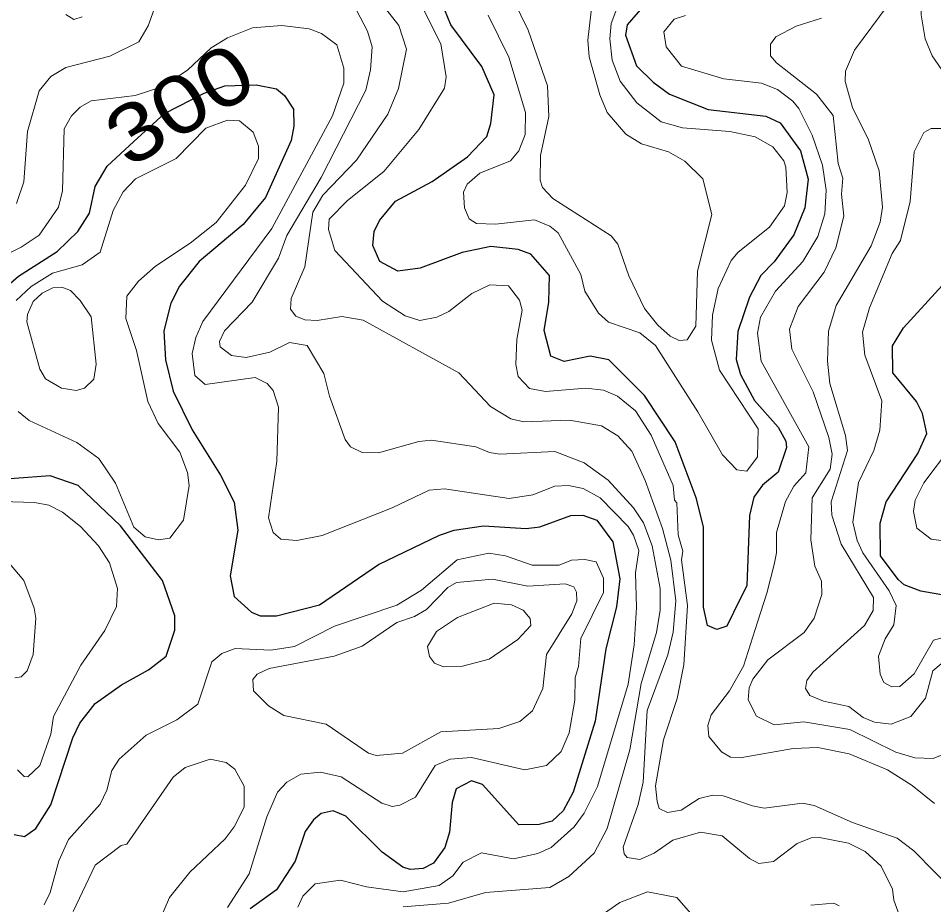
# Model space of a CAD drawing. Extents: x 673.6 to 698.9, y 7012 to 7040.1.
# Drawn here: x 684.723 to 685.993, y 7015.399 to 7016.628 of the extents above; entities that cross this region are included whole.
import ezdxf
from ezdxf.enums import TextEntityAlignment as Align

# ---------------------------------------------------------------- set-up
doc = ezdxf.new("R2010")
doc.units = 0
doc.header["$LTSCALE"] = 0.032
doc.layers.add('1', color=7, linetype='Continuous', lineweight=25)
doc.layers.add('2', color=7, linetype='Continuous', lineweight=13)
doc.layers.add('61', color=7, linetype='Continuous')

msp = doc.modelspace()

# ---------------------------------------------------------------- linework, layer by layer
at = {"layer": '1'}
for points in [[(685.7717, 7016.2906), (685.7529, 7016.2715), (685.7372, 7016.2417), (685.7212, 7016.1938), (685.7189, 7016.1552), (685.7249, 7016.1342), (685.7441, 7016.0984), (685.7771, 7016.061), (685.7876, 7016.0417), (685.7886, 7016.0331), (685.777, 7015.999), (685.7552, 7015.9808), (685.7432, 7015.964), (685.7376, 7015.9386), (685.7335, 7015.8419), (685.7153, 7015.8044), (685.7058, 7015.7855), (685.6923, 7015.7805), (685.679, 7015.7862), (685.6736, 7015.8118), (685.6735, 7015.923), (685.6635, 7015.9634), (685.6343, 7016.041), (685.5917, 7016.1051), (685.5425, 7016.1548), (685.5163, 7016.1595), (685.4802, 7016.1524), (685.4621, 7016.1595), (685.4526, 7016.1954), (685.4592, 7016.2345), (685.46, 7016.2715), (685.434, 7016.3011), (685.4168, 7016.3075), (685.3786, 7016.3117), (685.3391, 7016.3035), (685.2809, 7016.2816), (685.2495, 7016.2773), (685.2248, 7016.2907), (685.2151, 7016.3129), (685.217, 7016.3326), (685.2244, 7016.3479), (685.2466, 7016.3745), (685.2971, 7016.4018), (685.3461, 7016.436), (685.3732, 7016.4641), (685.3787, 7016.4822), (685.3832, 7016.522), (685.366, 7016.5611), (685.3233, 7016.6191), (685.3147, 7016.6393)], [(685.5892, 7016.6436), (685.5677, 7016.6191), (685.5652, 7016.6047), (685.5809, 7016.5624), (685.6037, 7016.5395), (685.6263, 7016.5228), (685.6802, 7016.5018), (685.7599, 7016.4924), (685.7799, 7016.4831)], [(684.705, 7016.2544), (684.7238, 7016.2708), (684.7771, 7016.3046), (684.8058, 7016.3323), (684.8223, 7016.3581), (684.8298, 7016.3951), (684.8465, 7016.4229), (684.8837, 7016.4572), (684.9263, 7016.496), (684.9813, 7016.5244), (685.0097, 7016.5345), (685.0532, 7016.536), (685.0816, 7016.5304), (685.0926, 7016.5212), (685.1048, 7016.5023), (685.1057, 7016.4786), (685.1016, 7016.4588), (685.0661, 7016.3796), (685.0354, 7016.3424), (684.9741, 7016.2908), (684.9469, 7016.2566), (684.9347, 7016.2333), (684.925, 7016.1946), (684.9274, 7016.1547), (684.9382, 7016.1112), (684.9644, 7016.0576), (685.0037, 7015.9945), (685.0229, 7015.9572), (685.0277, 7015.9182), (685.0172, 7015.8552), (685.0227, 7015.8264), (685.047, 7015.8046), (685.0586, 7015.7998), (685.0815, 7015.7998), (685.1411, 7015.815), (685.2228, 7015.8706), (685.3076, 7015.9114), (685.328, 7015.9182), (685.3683, 7015.9246), (685.4275, 7015.9206), (685.4467, 7015.9229), (685.4895, 7015.9387), (685.5064, 7015.9394), (685.5257, 7015.9323), (685.5479, 7015.9021), (685.5577, 7015.8508)], [(685.7799, 7016.4831), (685.8082, 7016.4444), (685.8189, 7016.405), (685.8141, 7016.3651), (685.7989, 7016.3281), (685.7717, 7016.2906)], [(685.975, 7015.8339), (685.9518, 7015.8428), (685.9434, 7015.8498), (685.919, 7015.8828), (685.9185, 7015.928), (685.9269, 7015.9579), (685.9708, 7016.0246), (685.9833, 7016.0525), (685.9771, 7016.08), (685.9688, 7016.0969), (685.936, 7016.1364), (685.9355, 7016.1741), (685.9511, 7016.199), (686.0047, 7016.2576)], [(684.7177, 7015.4966), (684.7319, 7015.4935), (684.7479, 7015.5046), (684.7684, 7015.5376), (684.7991, 7015.6304), (684.8089, 7015.651), (684.8298, 7015.678), (684.8667, 7015.704), (684.9041, 7015.7247), (684.9286, 7015.7438), (684.9405, 7015.78), (684.9406, 7015.7996), (684.9235, 7015.8487), (684.8649, 7015.9242), (684.8065, 7015.9805), (684.7676, 7015.9936), (684.668, 7015.9863)], [(685.5577, 7015.8508), (685.553, 7015.8122), (685.5383, 7015.7537), (685.5232, 7015.6535), (685.4928, 7015.555), (685.4791, 7015.5292)], [(686.1946, 7015.8512), (686.1607, 7015.8411), (686.1026, 7015.8392), (686.0479, 7015.8302), (686.0094, 7015.8278), (685.975, 7015.8339)], [(685.4791, 7015.5292), (685.4637, 7015.5151), (685.4456, 7015.5105), (685.4173, 7015.5099), (685.367, 7015.5659), (685.352, 7015.5707), (685.3307, 7015.5597), (685.3251, 7015.5408), (685.3214, 7015.4997), (685.3149, 7015.4785), (685.299, 7015.4567), (685.2849, 7015.4491), (685.2669, 7015.4481), (685.2567, 7015.4512), (685.2282, 7015.4721), (685.1778, 7015.5219), (685.16, 7015.5293), (685.1435, 7015.5257), (685.1326, 7015.5167), (685.1214, 7015.5006), (685.1074, 7015.4596), (685.0815, 7015.4196), (685.0447, 7015.3935)]]:
    msp.add_lwpolyline(points, dxfattribs=at)
at = {"layer": '2'}
for points in [[(685.2143, 7016.5886), (685.2075, 7016.6103), (685.1818, 7016.66), (685.1425, 7016.7188), (685.1023, 7016.7673), (685.0626, 7016.8407)], [(686.035, 7016.5117), (685.9907, 7016.5761), (685.9811, 7016.5998), (685.9753, 7016.6327), (685.9769, 7016.686), (685.9833, 7016.7198), (686.0017, 7016.7616)], [(684.9289, 7016.6886), (684.9035, 7016.6179), (684.8907, 7016.5957), (684.8501, 7016.5758), (684.7893, 7016.5601), (684.7686, 7016.5473), (684.7525, 7016.5277), (684.7362, 7016.4711), (684.731, 7016.4013), (684.7211, 7016.3714)], [(685.4031, 7016.2573), (685.3775, 7016.2584), (685.3524, 7016.2467), (685.3205, 7016.2215), (685.3039, 7016.2137), (685.2804, 7016.209), (685.2599, 7016.2157), (685.2285, 7016.2358), (685.1624, 7016.3063), (685.1535, 7016.3352), (685.1547, 7016.3494), (685.18, 7016.3753), (685.2304, 7016.4158), (685.2787, 7016.4738), (685.3145, 7016.5314), (685.3169, 7016.5468), (685.3092, 7016.5926), (685.2752, 7016.6612)], [(685.2274, 7016.648), (685.2512, 7016.6182), (685.2618, 7016.5851), (685.2508, 7016.5307), (685.2358, 7016.4954), (685.1922, 7016.4312), (685.1457, 7016.383), (685.1317, 7016.3595), (685.1206, 7016.2833), (685.102, 7016.2398), (685.1009, 7016.225), (685.1084, 7016.2149), (685.1207, 7016.21), (685.1378, 7016.2091), (685.1719, 7016.2147), (685.2015, 7016.2097), (685.3342, 7016.1366), (685.3783, 7016.0901)], [(685.3749, 7016.6326), (685.4036, 7016.5743), (685.4269, 7016.4973), (685.4262, 7016.4671), (685.4174, 7016.4444), (685.4058, 7016.4303), (685.3636, 7016.4134), (685.346, 7016.3983), (685.3409, 7016.387), (685.3421, 7016.3653), (685.3486, 7016.3502), (685.359, 7016.3438), (685.385, 7016.3425), (685.4391, 7016.3486), (685.4605, 7016.3398), (685.472, 7016.3308), (685.5035, 7016.2731), (685.5092, 7016.25), (685.5278, 7016.2191), (685.542, 7016.207), (685.5854, 7016.1919), (685.6069, 7016.1745), (685.6658, 7016.0823), (685.6998, 7016.0227), (685.72, 7016.0023), (685.7337, 7016.0002), (685.7486, 7016.0203), (685.7493, 7016.0587), (685.6959, 7016.1401), (685.6845, 7016.182), (685.686, 7016.2164), (685.6938, 7016.2533), (685.7121, 7016.2925), (685.7215, 7016.3038), (685.7651, 7016.3383), (685.786, 7016.3682), (685.7894, 7016.3866), (685.7879, 7016.4219), (685.785, 7016.4305), (685.7697, 7016.4498), (685.7454, 7016.4636), (685.7103, 7016.4712), (685.6445, 7016.4761), (685.6148, 7016.4847), (685.581, 7016.5111), (685.5582, 7016.541), (685.5467, 7016.57), (685.5438, 7016.5997), (685.5456, 7016.6207), (685.5576, 7016.6526)], [(685.5179, 7016.6378), (685.5134, 7016.5978), (685.5152, 7016.5748), (685.5296, 7016.522), (685.5401, 7016.4976), (685.5657, 7016.4673), (685.5875, 7016.454), (685.6251, 7016.4432), (685.6478, 7016.4302), (685.6725, 7016.4055), (685.685, 7016.3563), (685.6653, 7016.2777), (685.6629, 7016.2012), (685.6509, 7016.1821), (685.6398, 7016.1812), (685.6273, 7016.1872), (685.6101, 7016.2027), (685.5919, 7016.2256), (685.5702, 7016.2712), (685.5547, 7016.3151), (685.5457, 7016.3263), (685.4647, 7016.3783), (685.4502, 7016.3933), (685.447, 7016.4039), (685.4477, 7016.4378), (685.4591, 7016.4918), (685.4574, 7016.5343), (685.4303, 7016.6116), (685.4101, 7016.6537)], [(685.9298, 7016.6467), (685.883, 7016.584), (685.8707, 7016.5547), (685.8701, 7016.5405), (685.88, 7016.5046), (685.9025, 7016.4594), (685.9174, 7016.4168), (685.9217, 7016.3663), (685.9184, 7016.3455), (685.9061, 7016.3125), (685.8577, 7016.2299)], [(684.7893, 7016.6333), (684.8005, 7016.6265), (684.812, 7016.6301)], [(685.6485, 7016.6322), (685.6331, 7016.627), (685.6186, 7016.6093), (685.622, 7016.5886), (685.6433, 7016.5617), (685.7018, 7016.5444), (685.7541, 7016.5383), (685.7763, 7016.5295), (685.7974, 7016.5133), (685.806, 7016.5029), (685.8243, 7016.4663), (685.8387, 7016.4243), (685.8437, 7016.3898), (685.842, 7016.357), (685.8322, 7016.3257), (685.8114, 7016.291), (685.7736, 7016.2499), (685.7524, 7016.2136), (685.7485, 7016.1917), (685.7534, 7016.1527), (685.8195, 7016.0338), (685.8155, 7015.9979), (685.7988, 7015.9792), (685.7874, 7015.9582), (685.7748, 7015.9152), (685.7747, 7015.8872), (685.7714, 7015.8708), (685.7616, 7015.8309), (685.7486, 7015.791), (685.7289, 7015.7298), (685.7097, 7015.6957), (685.6844, 7015.6622), (685.6797, 7015.6477), (685.6811, 7015.6325), (685.6985, 7015.6112), (685.7108, 7015.6038), (685.7245, 7015.6029), (685.7977, 7015.6157), (685.8322, 7015.6173), (685.8757, 7015.6081), (685.9289, 7015.5863), (685.9631, 7015.5644), (685.9938, 7015.5395)], [(685.775, 7016.5662), (685.7667, 7016.5761), (685.7665, 7016.5924), (685.7741, 7016.6025), (685.8023, 7016.6173), (685.8371, 7016.6282)], [(684.6784, 7016.2861), (684.7272, 7016.3106), (684.7524, 7016.3274), (684.7791, 7016.3663), (684.7845, 7016.3889), (684.787, 7016.4749), (684.797, 7016.4927), (684.8092, 7016.5048), (684.8244, 7016.5136), (684.8855, 7016.5209), (684.9239, 7016.5336), (684.9579, 7016.5562), (684.9909, 7016.5871), (685.0137, 7016.6009), (685.0482, 7016.6149), (685.0887, 7016.6183)], [(685.0887, 7016.6183), (685.1268, 7016.6134), (685.1437, 7016.607), (685.1653, 7016.5914), (685.1748, 7016.559), (685.1748, 7016.5381)], [(685.257, 7015.3963), (685.3198, 7015.4013), (685.3711, 7015.4161), (685.4604, 7015.423), (685.4868, 7015.4384), (685.5219, 7015.4706), (685.5399, 7015.5046), (685.5713, 7015.614), (685.5873, 7015.7058), (685.6086, 7015.7764), (685.6136, 7015.8073), (685.6136, 7015.8375), (685.6026, 7015.8967), (685.5902, 7015.9286), (685.5764, 7015.9496), (685.5415, 7015.9877), (685.5081, 7016.0119), (685.4673, 7016.0273), (685.3912, 7016.0237), (685.3766, 7016.0259), (685.358, 7016.0339), (685.2964, 7016.043), (685.279, 7016.0414), (685.223, 7016.0255), (685.2004, 7016.0259), (685.1841, 7016.034), (685.1766, 7016.0443), (685.1549, 7016.1042), (685.1473, 7016.1357), (685.1238, 7016.1744), (685.0995, 7016.1785), (685.0722, 7016.1652), (685.0392, 7016.158), (685.0191, 7016.1607), (685.0033, 7016.1728), (685.0024, 7016.1802), (685.0093, 7016.1948), (685.0476, 7016.2347), (685.0841, 7016.2955), (685.0957, 7016.3268), (685.1433, 7016.4073), (685.2054, 7016.5285), (685.2116, 7016.5567), (685.2143, 7016.5886)], [(685.8651, 7016.3845), (685.8666, 7016.4064), (685.8603, 7016.4269), (685.8534, 7016.4932), (685.8305, 7016.5229), (685.775, 7016.5662)], [(685.1748, 7016.5381), (685.1591, 7016.493), (685.0751, 7016.3369), (684.9794, 7016.2076), (684.9697, 7016.1855), (684.9645, 7016.1634), (684.9681, 7016.1328), (684.9827, 7016.1204), (685.052, 7016.1301), (685.0683, 7016.1217), (685.0769, 7016.1122), (685.0844, 7016.089), (685.082, 7016.0142), (685.0705, 7015.9356), (685.077, 7015.9152), (685.0876, 7015.906), (685.1095, 7015.904), (685.1448, 7015.911), (685.2419, 7015.9492), (685.2932, 7015.9739), (685.3145, 7015.9756), (685.404, 7015.9625), (685.4369, 7015.9676), (685.4673, 7015.9796), (685.4862, 7015.9805), (685.5069, 7015.9764), (685.5301, 7015.9631), (685.569, 7015.9233), (685.5766, 7015.9115), (685.5839, 7015.8904), (685.5792, 7015.8593), (685.5808, 7015.8114), (685.5774, 7015.7596), (685.5689, 7015.7049), (685.5264, 7015.5628), (685.5083, 7015.5262), (685.4944, 7015.5072), (685.4622, 7015.4786), (685.4437, 7015.4701), (685.4099, 7015.4629), (685.3658, 7015.4709), (685.3405, 7015.4583), (685.326, 7015.4393), (685.3069, 7015.4257), (685.2573, 7015.4169), (685.2061, 7015.4239), (685.17, 7015.4332), (685.1351, 7015.4281), (685.1181, 7015.411), (685.1112, 7015.3957)], [(684.7233, 7016.0828), (684.7385, 7016.0705), (684.8047, 7016.0399), (684.8352, 7016.0178), (684.8584, 7015.9838), (684.8837, 7015.9227), (684.8994, 7015.9091), (684.9178, 7015.905), (684.9333, 7015.9073), (684.9523, 7015.9321), (684.9603, 7015.9805), (684.9578, 7015.9986), (684.9472, 7016.0266), (684.9174, 7016.0663), (684.9032, 7016.0967), (684.8874, 7016.1673), (684.8725, 7016.212), (684.8741, 7016.2427), (684.8902, 7016.2638), (684.9137, 7016.2843), (684.9616, 7016.3164), (684.9979, 7016.3451), (685.0386, 7016.3966), (685.0563, 7016.4338), (685.0564, 7016.451), (685.0491, 7016.4701), (685.0302, 7016.486), (685.0136, 7016.4867), (684.9836, 7016.4758), (684.9425, 7016.4336), (684.8858, 7016.4054), (684.8688, 7016.3876), (684.855, 7016.3615), (684.8371, 7016.3037), (684.8121, 7016.2861), (684.7709, 7016.2748), (684.7412, 7016.2564), (684.7206, 7016.237)], [(686.0265, 7015.7751), (685.9924, 7015.7658), (685.9655, 7015.7192), (685.9458, 7015.7018), (685.9346, 7015.7011), (685.9237, 7015.707), (685.9184, 7015.7188), (685.9161, 7015.7436), (685.9256, 7015.7678), (685.9377, 7015.7873), (685.9406, 7015.8141), (685.931, 7015.8343), (685.8946, 7015.8872), (685.8865, 7015.904), (685.8807, 7015.9293), (685.8884, 7015.9845), (685.9097, 7016.0289), (685.9183, 7016.0571), (685.9209, 7016.0977), (685.8972, 7016.1611), (685.8942, 7016.1931), (685.9036, 7016.2268), (685.9354, 7016.302), (685.9468, 7016.3202), (685.9604, 7016.3743), (685.9656, 7016.4431), (685.979, 7016.4696), (685.9894, 7016.4751), (686.0047, 7016.4752)], [(686.0347, 7015.6189), (685.992, 7015.6018), (685.9667, 7015.6029), (685.9401, 7015.6105), (685.8763, 7015.642), (685.8129, 7015.6526), (685.7715, 7015.6487), (685.7472, 7015.6605), (685.7353, 7015.6831), (685.737, 7015.6999), (685.7419, 7015.7118), (685.7629, 7015.7386), (685.813, 7015.7765), (685.8272, 7015.7965), (685.8379, 7015.8293), (685.8371, 7015.8478), (685.8281, 7015.8683), (685.8224, 7015.905), (685.8245, 7015.9632), (685.8493, 7016.0032), (685.8519, 7016.0237), (685.8476, 7016.0471), (685.8256, 7016.1104), (685.7961, 7016.1694), (685.7928, 7016.1971), (685.805, 7016.2284), (685.841, 7016.2761), (685.8571, 7016.3099), (685.8683, 7016.3536), (685.8651, 7016.3845)], [(685.4165, 7016.1313), (685.4132, 7016.1479), (685.4148, 7016.1827), (685.422, 7016.2235), (685.4186, 7016.2372), (685.4031, 7016.2573)], [(685.8577, 7016.2299), (685.8471, 7016.1942), (685.8454, 7016.1527), (685.8487, 7016.1216), (685.8707, 7016.0499), (685.8732, 7016.029)], [(686.0237, 7015.4145), (685.9652, 7015.4739), (685.9423, 7015.4916), (685.8804, 7015.5131), (685.8272, 7015.5368), (685.8108, 7015.5398), (685.7579, 7015.5331), (685.7415, 7015.536), (685.7007, 7015.5499), (685.6865, 7015.5508), (685.6678, 7015.5466), (685.6428, 7015.5303), (685.6237, 7015.527), (685.612, 7015.5323), (685.6093, 7015.5422), (685.6072, 7015.5641), (685.6183, 7015.6277), (685.637, 7015.6848), (685.6465, 7015.7315), (685.6515, 7015.814), (685.6433, 7015.8771), (685.6447, 7015.8892), (685.6383, 7015.9119), (685.6366, 7015.9564), (685.6334, 7015.9598), (685.6317, 7015.9802), (685.6009, 7016.0502), (685.5791, 7016.084), (685.5541, 7016.104), (685.535, 7016.1127), (685.5106, 7016.1154), (685.4547, 7016.1105), (685.4323, 7016.115), (685.4165, 7016.1313)], [(685.3783, 7016.0901), (685.4064, 7016.0726), (685.4246, 7016.0686), (685.4879, 7016.0709), (685.5323, 7016.0629), (685.5547, 7016.0493)], [(685.5547, 7016.0493), (685.5741, 7016.0281), (685.5929, 7015.9874), (685.6167, 7015.9205), (685.6285, 7015.8767), (685.635, 7015.8204), (685.6317, 7015.7768), (685.6239, 7015.7456), (685.5956, 7015.6683), (685.5898, 7015.5688), (685.5828, 7015.538), (685.5622, 7015.479), (685.5636, 7015.4695), (685.5677, 7015.4644), (685.5851, 7015.4617), (685.6054, 7015.4704), (685.6312, 7015.4884), (685.6695, 7015.4998), (685.6996, 7015.4945), (685.7376, 7015.4632), (685.7504, 7015.4563), (685.7707, 7015.459), (685.8037, 7015.4841), (685.8231, 7015.4917), (685.8345, 7015.4923), (685.8746, 7015.4843), (685.8976, 7015.4729), (685.9198, 7015.4524), (685.9356, 7015.4206), (685.9375, 7015.4053), (685.9493, 7015.3736)], [(686.0142, 7015.9025), (685.9894, 7015.9058), (685.9695, 7015.921), (685.9646, 7015.9441), (685.9671, 7015.9599), (685.979, 7015.9841), (686.0249, 7016.0448)], [(685.8732, 7016.029), (685.8504, 7015.9575), (685.8517, 7015.939), (685.8646, 7015.8991), (685.9092, 7015.8251), (685.9087, 7015.8071), (685.8969, 7015.7864), (685.8253, 7015.7214), (685.8167, 7015.7101), (685.8151, 7015.6989), (685.8212, 7015.6894), (685.8398, 7015.6813), (685.8749, 7015.6739), (685.8948, 7015.6589), (685.9105, 7015.6522), (685.9338, 7015.6495), (685.9613, 7015.6602), (685.9815, 7015.6856), (685.9918, 7015.7232), (686.0032, 7015.7331)], [(684.7221, 7015.5862), (684.7314, 7015.577), (684.7364, 7015.5764), (684.7531, 7015.592), (684.7685, 7015.6358), (684.7723, 7015.6603), (684.81, 7015.7312), (684.8432, 7015.7791), (684.8594, 7015.8126), (684.8609, 7015.8375), (684.8497, 7015.873), (684.8346, 7015.8967), (684.8096, 7015.9233), (684.7847, 7015.9433), (684.7657, 7015.9532), (684.7458, 7015.9567), (684.6688, 7015.9592)], [(685.0056, 7015.7472), (685.024, 7015.7545), (685.0737, 7015.7522), (685.1062, 7015.7572), (685.162, 7015.7851), (685.2484, 7015.8145), (685.2826, 7015.8354), (685.3319, 7015.8773), (685.3761, 7015.8867), (685.3988, 7015.8828), (685.4361, 7015.8697), (685.4736, 7015.8697), (685.4906, 7015.877), (685.5092, 7015.8778), (685.5246, 7015.8744), (685.5347, 7015.852), (685.5347, 7015.8322), (685.5037, 7015.768), (685.5002, 7015.7292), (685.4954, 7015.7143), (685.4953, 7015.6828), (685.4871, 7015.6374), (685.4762, 7015.6114), (685.4557, 7015.5921), (685.4258, 7015.5862), (685.352, 7015.6033), (685.3224, 7015.6008), (685.3017, 7015.5921), (685.2741, 7015.5484), (685.2525, 7015.5371), (685.2418, 7015.5353), (685.2276, 7015.5397), (685.1712, 7015.5763), (685.1423, 7015.5827), (685.1154, 7015.5803), (685.096, 7015.5688), (685.083, 7015.5552), (685.068, 7015.5208), (685.0435, 7015.4419), (685.0135, 7015.3952)], [(684.7111, 7015.8723), (684.7311, 7015.8488), (684.7456, 7015.8103), (684.7475, 7015.7965), (684.7442, 7015.7459), (684.7359, 7015.7235), (684.7274, 7015.7151), (684.7184, 7015.7136)], [(684.8634, 7015.601), (684.9009, 7015.6343), (684.9434, 7015.6553), (684.9723, 7015.6773), (684.992, 7015.7357), (685.0056, 7015.7472)], [(684.7592, 7015.3991), (684.7675, 7015.416), (684.7797, 7015.4599), (684.7929, 7015.4895), (684.8369, 7015.5385), (684.8461, 7015.5578), (684.8529, 7015.585), (684.8634, 7015.601)], [(684.9198, 7015.3783), (684.9331, 7015.4092), (684.9614, 7015.4442), (685.0102, 7015.4905), (685.0226, 7015.5069), (685.0366, 7015.5345), (685.0367, 7015.5636), (685.0238, 7015.587), (685.0115, 7015.5963), (684.9893, 7015.6009), (684.9547, 7015.5894), (684.938, 7015.576), (684.8737, 7015.4832), (684.8662, 7015.4813), (684.8299, 7015.454), (684.7996, 7015.3896)], [(685.6841, 7015.3546), (685.6367, 7015.4092), (685.5958, 7015.4168), (685.5577, 7015.402), (685.5015, 7015.3633)], [(685.8619, 7015.3977), (685.8544, 7015.4013), (685.8224, 7015.3987)]]:
    msp.add_lwpolyline(points, dxfattribs=at)
for points in [[(684.7834, 7016.1153), (684.7613, 7016.1281), (684.7532, 7016.1417), (684.7352, 7016.2073), (684.7361, 7016.2174), (684.7438, 7016.2356), (684.7564, 7016.2472), (684.7713, 7016.2546), (684.7839, 7016.2554), (684.7956, 7016.2505), (684.8091, 7016.2369), (684.8245, 7016.2142), (684.8313, 7016.1486), (684.828, 7016.128), (684.8154, 7016.1153), (684.8036, 7016.1122)], [(685.1501, 7015.6493), (685.0917, 7015.6615), (685.0702, 7015.6748), (685.0495, 7015.6956), (685.0488, 7015.7115), (685.0547, 7015.7188), (685.0712, 7015.7265), (685.1613, 7015.7439), (685.2004, 7015.7575), (685.2483, 7015.7903), (685.2729, 7015.7988), (685.2896, 7015.8083), (685.3192, 7015.8389), (685.3312, 7015.8458), (685.3809, 7015.8506), (685.4301, 7015.8409), (685.4816, 7015.8442), (685.4936, 7015.8399), (685.4976, 7015.8324), (685.498, 7015.8205), (685.4909, 7015.8024), (685.456, 7015.746), (685.4509, 7015.6989), (685.4365, 7015.6678), (685.4187, 7015.6531), (685.3898, 7015.6436), (685.3093, 7015.6386), (685.2564, 7015.6094), (685.2196, 7015.6059), (685.209, 7015.6093)], [(685.2936, 7015.7432), (685.2908, 7015.7569), (685.3034, 7015.7779), (685.3326, 7015.7973), (685.3835, 7015.817), (685.4073, 7015.8151), (685.4235, 7015.8075), (685.4332, 7015.7959), (685.434, 7015.7862), (685.4161, 7015.7666), (685.3762, 7015.7396), (685.3395, 7015.73), (685.3128, 7015.729), (685.3007, 7015.7341)]]:
    msp.add_lwpolyline(points, close=True, dxfattribs=at)

# ---------------------------------------------------------------- texts
at = {"layer": '61', "width": 1.2}
msp.add_text('300', height=0.08, rotation=31.35, dxfattribs=at).set_placement((684.968, 7016.4746), align=Align.CENTER)

doc.saveas('drawing.dxf')
